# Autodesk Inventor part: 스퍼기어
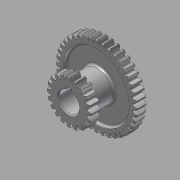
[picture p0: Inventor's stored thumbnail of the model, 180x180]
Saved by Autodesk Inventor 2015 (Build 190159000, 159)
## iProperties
Created: 2015-09
Part Number: 스퍼기어
Material: 강철, 연강
Document SubType Name: Modeling
Designer: mduedu
Density: 7.86 g/cm^3
Mass: 345.726 g
Surface Area: 225.641 cm^2
Volume: 43.9855 cm^3
Appearance: 강철
Author: mduedu
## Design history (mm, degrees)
sketch "스케치1"
  geometry: C1 r 38 at (0, 0); C2 r 40 at (0, 0); C3 r 35.5 at (0, 0); 1 further point
  constraints: 3 centre point, 3 coincident
  dimensions: "d0" = 76 diameter of C1; "d2" = 2 radial gap between concentric circles of C2 C1; "d3" = 71 diameter of C3 (computed from d0)
extrude "돌출1" new body sketch "스케치1" stored distance "d4" = 10; taper "d5" = 0 deg
sketch "스케치2"
  geometry: L1 (0, 35.5)-(0, -35.5); L2 (0, 0)-(40, 0); L3 (0, 0.57)-(39.996, 0.57); L4 (0, 1.57)-(39.969, 1.57); L5 (0, 2.07)-(39.946, 2.07); A1 r 35.5 centre (0, 0) between (0, 35.5) and (0, -35.5) reference; A2 r 40 centre (0, 0) between (40, 0) and (39.946, 2.07) reference; A3 r 9.234 centre (34.93, -7.149) between (39.996, 0.57) and (35.44, 2.07); A4 r 9.234 centre (34.93, 7.149) between (35.44, -2.07) and (39.996, -0.57); A5 r 40 centre (0, 0) between (39.996, -0.57) and (39.996, 0.57); A6 r 35.5 centre (0, 0) between (35.44, -2.07) and (35.44, 2.07); 4 further points
  constraints: 16 point on circle, 10 end point, 6 point on line, 4 centre point, 3 coincident, 3 parallel, 3 symmetric about line, 2 midpoint, 1 perpendicular, 1 vertical, 3 other
  dimensions: "d6" = 0.5 distance between parallel lines of L4 L5; "d8" = 1 distance between parallel lines of L3 L4; "d9" = 1.57 distance between parallel lines of L2 L4
extrude "돌출2" join sketch "스케치2" distance "d10" = 5; taper "d12" = 0 deg; dims "d11" = 5, "d13" = 0
fillet "모깎기1" dims "d17" = 0.5
chamfer "모따기1" distance "d21" = 1; stored, may be unused: second distance "d22" = 2, angle "d23" = 45 deg
sketch "스케치3"
  geometry: C1 r 32.5 at (0, 0); C2 r 15 at (0, 0); 1 further point
  constraints: 2 centre point, 2 coincident
  dimensions: "d27" = 65 diameter of C1; "d28" = 30 diameter of C2
extrude "돌출3" cut sketch "스케치3" distance "d29" = 3; taper "d30" = 0 deg
fillet "모깎기2" dims "d31" = 2
node "작업 평면2"
  node "작업 평면1"
sketch "스케치4"
  geometry: C1 r 15 at (0, 0) reference; 1 further point
extrude "돌출4" join sketch "스케치4" stored distance "d34" = 3; taper "d35" = 0 deg
sketch "스케치5"
  geometry: C1 r 17.5 at (0, 0); C2 r 20 at (0, 0); C3 r 22 at (0, 0); 1 further point
  constraints: 3 centre point, 3 coincident
  dimensions: "d36" = 40 diameter of C2; "d38" = 2 radial gap between concentric circles of C2 C3; "d39" = 35 diameter of C1 (= d36 - 2.5 x d38)
extrude "돌출6" join sketch "스케치5" distance "d46" = 10; taper "d47" = 0 deg
sketch "스케치6"
  geometry: L1 (0, 0)-(0, 22); L2 (-17.5, 0)-(17.5, 0); L3 (-0.57, 0)-(-0.57, 21.993); L4 (-1.57, 0)-(-1.57, 21.944); L5 (-2.07, 0)-(-2.07, 21.902); A1 r 22 centre (0, 0) between (0, 22) and (-0.57, 21.993) reference; A2 r 17.5 centre (0, 0) between (-17.5, 0) and (17.5, 0) reference; A3 r 9.431 centre (7.348, 16.868) between (-0.57, 21.993) and (-2.07, 17.377); A4 r 9.431 centre (-7.348, 16.868) between (2.07, 17.377) and (0.57, 21.993); A5 r 17.5 centre (0, 0) between (2.07, 17.377) and (-2.07, 17.377); A6 r 22 centre (0, 0) between (0.57, 21.993) and (-0.57, 21.993); 4 further points
  constraints: 16 point on circle, 10 end point, 5 point on line, 4 centre point, 3 coincident, 3 symmetric about line, 2 parallel, 2 perpendicular, 1 midpoint, 1 vertical, 3 other
  dimensions: "d40" = 0.5 distance between parallel lines of L4 L5; "d42" = 1 distance between parallel lines of L3 L4; "d43" = 1.57 distance between parallel lines of L1 L4
extrude "돌출5" join sketch "스케치6" distance "d44" = 10; taper "d45" = 0 deg
fillet "모깎기3" dims "d48" = 0.5
chamfer "모따기2" distance "d49" = 1; stored, may be unused: second distance "d50" = 2, angle "d51" = 45 deg
sketch "스케치7"
  geometry: C1 r 10 at (0, 0); 1 further point
  constraints: 1 centre point, 1 coincident
  dimensions: "d55" = 20 diameter of C1
extrude "돌출7" cut sketch "스케치7" stored distance "d56" = 10; taper "d57" = 0 deg
sketch "스케치8"
  geometry: L1 (-9.539, -3)-(-12.8, -3); L2 (-12.8, -3)-(-12.8, 3); L3 (-12.8, 3)-(-9.539, 3); L4 (-9.539, 3)-(-9.539, -3); A1 r 10 centre (0, 0) between (-9.539, -3) and (-9.539, 3) reference; 2 further points
  constraints: 8 end point, 3 point on circle, 2 parallel, 1 horizontal, 1 horizontal alignment, 1 perpendicular
  dimensions: "d58" = 6 distance of L1.end L2.end; "d60" = 22.8 distance from line of point (10, 0) L2
extrude "돌출8" cut sketch "스케치8" stored distance "d61" = 10; taper "d62" = 0 deg
chamfer "모따기3" distance "d63" = 1; stored, may be unused: second distance "d64" = 2, angle "d65" = 45 deg
fillet "모깎기4" dims "d66" = 2
node "솔리드1"
pattern_circular "원형 패턴3" dims "d25" = 360 deg
mirror "대칭1"
pattern_circular "원형 패턴4" dims "d53" = 360 deg
other parameters: "d32" = 5, "d33" = 42
